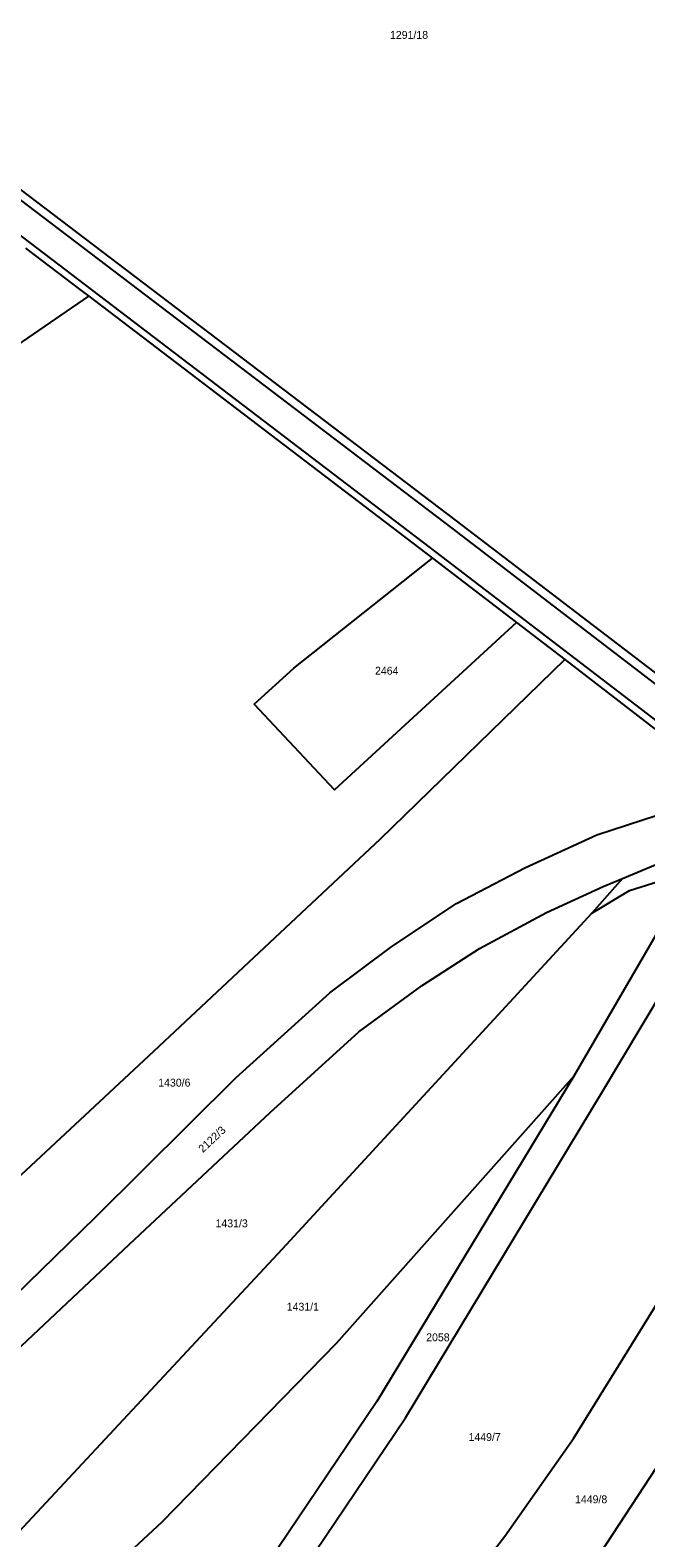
# Model space of a CAD drawing. Extents: x -679220 to -673243, y -1075091 to -1066557.
# Drawn here: x -677370.2 to -677237.5, y -1070909.6 to -1070584.9 of the extents above; entities that cross this region are included whole.
import ezdxf

# ---------------------------------------------------------------- set-up
doc = ezdxf.new("R2010")
doc.units = 0
for name, color, linetype in [('Hranice parcel', 7, 'Continuous'), ('Parcelní čísla', 7, 'Continuous'), ('Vnitřní kresba', 7, 'Continuous')]:
    doc.layers.add(name, color=color, linetype=linetype)

msp = doc.modelspace()

# ---------------------------------------------------------------- linework, layer by layer
at = {"layer": 'Hranice parcel'}
for p, q in [((-677357.58, -1070642.17), (-677283.49, -1070698.63)), ((-677283.49, -1070698.63), (-677265.37, -1070712.46)), ((-677265.37, -1070712.46), (-677254.95, -1070720.42)), ((-677254.95, -1070720.42), (-677222.65, -1070745.38)), ((-677227.25, -1070765.88), (-677252.98, -1070810.18)), ((-677242.5, -1070767.63), (-677249.13, -1070775.06))]:
    msp.add_line(p, q, dxfattribs=at)
for points in [[(-677229.27, -1070728.01), (-677278.26, -1070690.56), (-677374.15, -1070617.77), (-677453.8, -1070557.3)], [(-677371.21, -1070631.84), (-677359.19, -1070640.94), (-677357.58, -1070642.17)], [(-677525.71, -1070755.57), (-677433.57, -1070694.28), (-677357.58, -1070642.17)], [(-677265.37, -1070712.46), (-677304.56, -1070748.48), (-677321.88, -1070730.05), (-677313.34, -1070722.32), (-677283.49, -1070698.63)], [(-677430.41, -1070885.62), (-677343.57, -1070804.78), (-677294.64, -1070759.08), (-677254.95, -1070720.42)], [(-677419.36, -1070901.45), (-677399.79, -1070883.04), (-677356.1, -1070840.53), (-677325.87, -1070810.52), (-677305.6, -1070792.25), (-677292.22, -1070782.24), (-677278.31, -1070773.02), (-677263.52, -1070765.35), (-677248.06, -1070758.21), (-677228.39, -1070751.81)], [(-677242.5, -1070767.63), (-677227.93, -1070761.51), (-677217.09, -1070756.97)], [(-677414.37, -1070908.39), (-677394.15, -1070888.97), (-677348.79, -1070846.41), (-677318.47, -1070818.03), (-677299.31, -1070800.67), (-677285.69, -1070790.64), (-677273.33, -1070782.72), (-677258.9, -1070774.96), (-677246.69, -1070769.37), (-677242.5, -1070767.63)], [(-677249.13, -1070775.06), (-677240.98, -1070770.18), (-677227.25, -1070765.88)], [(-677249.13, -1070775.06), (-677315.84, -1070847.44), (-677379.6, -1070915.76), (-677398.1, -1070933.96)], [(-677364.04, -1070987.23), (-677362.94, -1070980.54), (-677338.56, -1070950.82), (-677313.04, -1070919.03), (-677289.25, -1070883.76), (-677247.04, -1070813.86), (-677224.46, -1070776.16)], [(-677353.59, -1071009.21), (-677311.42, -1070962.52), (-677281.85, -1070927.39), (-677267.88, -1070909.25), (-677253.05, -1070888.24), (-677185.28, -1070778.87)], [(-677340.87, -1071024.47), (-677300.46, -1070979.79), (-677271.33, -1070945.13), (-677251.29, -1070919.02), (-677223.02, -1070875.98), (-677171.84, -1070788.87)], [(-677388.94, -1070948.54), (-677365.95, -1070928.7), (-677341.75, -1070906.21), (-677304.14, -1070867.74), (-677252.98, -1070810.18)], [(-677252.98, -1070810.18), (-677295.44, -1070880.3), (-677318.81, -1070914.88), (-677343.42, -1070946.65), (-677369.35, -1070977.11)]]:
    msp.add_lwpolyline(points, dxfattribs=at)
at = {"layer": 'Vnitřní kresba'}
for p, q in [((-677385.13, -1070611.8), (-677279.29, -1070692.15)), ((-677282.66, -1070697.35), (-677388.72, -1070616.61)), ((-677279.29, -1070692.15), (-677218.48, -1070738.73)), ((-677214.9, -1070749.15), (-677282.66, -1070697.35))]:
    msp.add_line(p, q, dxfattribs=at)

# ---------------------------------------------------------------- texts
at = {"layer": 'Parcelní čísla'}
for s, p in [('1291/18', (-677292.63, -1070586.75)), ('2464', (-677295.86, -1070723.71)), ('1430/6', (-677342.6, -1070812.44)), ('1431/3', (-677330.24, -1070842.75)), ('1431/1', (-677314.89, -1070860.7)), ('2058', (-677284.82, -1070867.29)), ('1449/7', (-677275.69, -1070888.78)), ('1449/8', (-677252.74, -1070902.19))]:
    msp.add_text(s, height=1.7, dxfattribs=at).set_placement(p)
msp.add_text('2122/3', height=1.7, rotation=43, dxfattribs=at).set_placement((-677332.97, -1070826.77))

doc.saveas('drawing.dxf')
